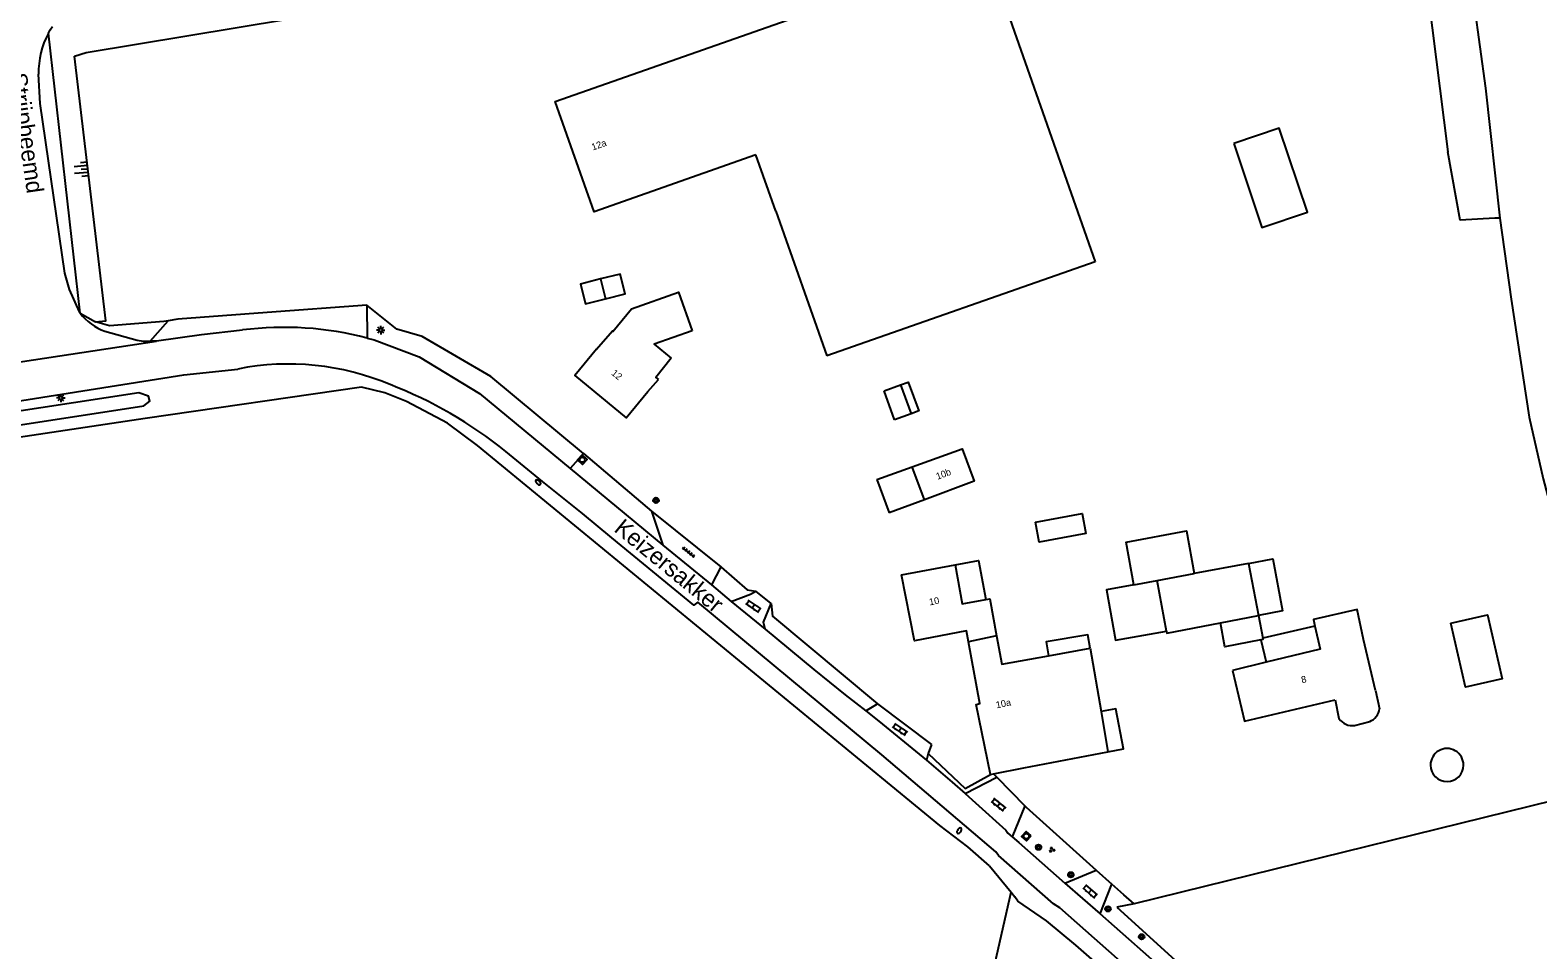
# Model space of a CAD drawing. Extents: x 124000 to 129000, y 395500 to 397503.
# Drawn here: x 126092.4 to 126314, y 397168.2 to 397303.4 of the extents above; entities that cross this region are included whole.
import ezdxf

# ---------------------------------------------------------------- set-up
doc = ezdxf.new("R2010")
doc.units = 0
for name, color, linetype in [('gg-afsc-draadraster', 7, 'Continuous'), ('gg-afsc-erfafscheiding', 7, 'Continuous'), ('gg-afsc-hekwerk', 7, 'Continuous'), ('gg-anno-huisnummerreeks BGT', 7, 'Continuous'), ('gg-anno-openbare ruimte label', 7, 'Continuous'), ('gg-bbg-bijgebouw', 7, 'Continuous'), ('gg-bbg-gedigitaliseerde bebouwing', 7, 'Continuous'), ('gg-bbg-gedigitaliseerde bijgebouw', 7, 'Continuous'), ('gg-bbg-hoofdgebouw', 7, 'Continuous'), ('gg-bbg-luifel en loopbrug', 7, 'Continuous'), ('gg-bbg-onder overbouw', 7, 'Continuous'), ('gg-bbg-pand overbouw', 7, 'Continuous'), ('gg-bbg-tussenscheiding', 7, 'Continuous'), ('gg-knt-BGT kruinlijn', 7, 'Continuous'), ('gg-knt-bovenkant onderkant talud', 7, 'Continuous'), ('gg-knt-bronhoudergrens', 7, 'Continuous'), ('gg-knt-verharding', 7, 'Continuous'), ('gg-knt-verharding nz', 7, 'Continuous'), ('gg-kntw-greppel-droge sloot', 7, 'Continuous'), ('gg-kwrk-keermuur', 7, 'Continuous'), ('gt-grn-weggrens', 7, 'Continuous'), ('gt-symb-boom', 7, 'Continuous'), ('gt-symb-brandkraan', 7, 'Continuous'), ('gt-symb-groenvak', 7, 'Continuous'), ('gt-symb-klinker verharding', 7, 'Continuous'), ('gt-symb-lichtmast', 7, 'Continuous'), ('gt-symb-rioolschacht', 7, 'Continuous'), ('gt-symb-talud symbool', 7, 'Continuous'), ('gt-symb-tegel verharding', 7, 'Continuous'), ('gx-grn-maaiveld', 7, 'Continuous')]:
    doc.layers.add(name, color=color, linetype=linetype)

# ---------------------------------------------------------------- blocks, each defined once
blk = doc.blocks.new('gt0-LMAST')
at = {"layer": 'gt-symb-lichtmast'}
for p, q in [((-0.18, 0.17), (-0.45, 0.44)), ((-0.01, 0.25), (-0.01, 0.62)), ((0.17, 0.17), (0.44, 0.44)), ((-0.26, 0), (-0.63, 0)), ((-0.18, -0.18), (-0.45, -0.45)), ((-0.01, -0.25), (-0.01, -0.63)), ((0.44, -0.45), (0.17, -0.18)), ((0.24, 0), (0.62, 0))]:
    blk.add_line(p, q, dxfattribs=at)
blk.add_circle((-0.01, 0), 0.25, dxfattribs=at)
blk = doc.blocks.new('gt0-TEG1')
at = {"layer": 'gt-symb-tegel verharding'}
for p, q in [((-1.12, 0), (1.13, 0)), ((-0.9, -0.25), (-0.9, 0.25)), ((-0.45, -0.25), (-0.45, 0.25)), ((0, -0.25), (0, 0.25)), ((0.45, -0.25), (0.45, 0.25)), ((0.9, -0.25), (0.9, 0.25))]:
    blk.add_line(p, q, dxfattribs=at)
blk = doc.blocks.new('gt0-BOOM')
at = {"layer": 'gt-symb-boom'}
for radius in [0.4, 0.2]:
    blk.add_circle((0, 0), radius, dxfattribs=at)
blk = doc.blocks.new('gt0-BR')
at = {"layer": 'gt-symb-brandkraan'}
for centre, radius, start, end in [((-0.24, 0), 0.206, 107.5669, 252.4331), ((0.6, -2.66), 3, 106.892, 107.5669), ((0, -0.69), 0.938, 73.108, 106.892), ((-0.6, -2.66), 3, 72.4331, 73.108), ((0.24, 0), 0.206, 287.567, 72.4331), ((0.6, 2.66), 3, 252.4331, 253.108), ((0, 0.69), 0.938, 253.108, 286.8921), ((-0.6, 2.66), 3, 286.8921, 287.567)]:
    blk.add_arc(centre, radius, start, end, dxfattribs=at)
blk = doc.blocks.new('gt0-RS')
at = {"layer": 'gt-symb-rioolschacht'}
blk.add_lwpolyline([(-0.5, -0.5), (0.5, -0.5), (0.5, 0.5), (-0.5, 0.5)], close=True, dxfattribs=at)
blk.add_circle((0, 0), 0.375, dxfattribs=at)
blk = doc.blocks.new('gt0-KL1')
at = {"layer": 'gt-symb-klinker verharding'}
for p, q in [((-1.15, 0.3), (1.15, 0.3)), ((-1, -0.3), (-1, 0.3)), ((-0.5, 0.3), (-0.5, 0.45)), ((0, -0.3), (0, 0.3)), ((0.5, 0.3), (0.5, 0.45)), ((1, -0.3), (1, 0.3)), ((-1.15, -0.3), (1.15, -0.3)), ((-0.5, -0.45), (-0.5, -0.3)), ((0.5, -0.45), (0.5, -0.3))]:
    blk.add_line(p, q, dxfattribs=at)
blk = doc.blocks.new('gt0-GRVAK')
at = {"layer": 'gt-symb-groenvak'}
for p, q in [((-0.11, 0.19), (-0.23, 0.24)), ((-0.18, 0.15), (0.09, 0.15)), ((-0.09, 0.21), (-0.16, 0.32)), ((-0.05, 0.21), (-0.05, 0.39)), ((0, 0.21), (0.06, 0.32)), ((0.01, 0.19), (0.13, 0.24)), ((0.26, -0.05), (0.2, 0.06)), ((0.3, -0.05), (0.3, 0.13)), ((0.35, -0.05), (0.41, 0.06)), ((-0.25, -0.23), (-0.36, -0.18)), ((-0.32, -0.26), (-0.05, -0.26)), ((-0.23, -0.21), (-0.29, -0.09)), ((-0.18, -0.2), (-0.18, -0.02)), ((-0.14, -0.21), (-0.07, -0.09)), ((-0.12, -0.23), (0, -0.18)), ((0.24, -0.07), (0.12, -0.02)), ((0.17, -0.11), (0.44, -0.11)), ((0.37, -0.07), (0.49, -0.02))]:
    blk.add_line(p, q, dxfattribs=at)
blk = doc.blocks.new('gt0-TALUD_1')
at = {"layer": 'gt-symb-talud symbool'}
for p, q in [((-1, -1), (-1, 0)), ((-0.5, -2), (-0.5, 0)), ((0, -1), (0, 0)), ((0.5, -2), (0.5, 0)), ((1, -1), (1, 0))]:
    blk.add_line(p, q, dxfattribs=at)

msp = doc.modelspace()

# ---------------------------------------------------------------- linework, layer by layer
at = {"layer": 'gg-afsc-draadraster'}
msp.add_lwpolyline([(126226.52, 397135.32), (126232.25, 397157.74), (126236.57, 397176.71)], dxfattribs=at)
at = {"layer": 'gg-afsc-erfafscheiding'}
for points in [[(126158.14, 397242.37), (126153.73, 397245.64), (126147.71, 397248.83), (126144.52, 397250.13), (126141.08, 397250.94), (126109.27, 397246.32), (126072.36, 397240.79), (125997.79, 397229.41), (125963.14, 397224.23), (125959.14, 397223.42)], [(126233.39, 397180.61), (126230.21, 397183.36), (126226.11, 397186.54), (126158.14, 397242.37)], [(126193.91, 397224.52), (126193.94, 397224.5), (126197.76, 397221.16), (126199.07, 397220.94)], [(126201.31, 397219.16), (126201.48, 397217.28), (126216.95, 397204.39)], [(126224.37, 397197.12), (126229.82, 397191.97), (126233.53, 397194.01)], [(126263.89, 397151.77), (126253.93, 397162.07), (126246.09, 397168.94), (126241.75, 397172.5), (126237.55, 397175.38), (126237.14, 397176.02)]]:
    msp.add_lwpolyline(points, dxfattribs=at)
at = {"layer": 'gg-afsc-hekwerk'}
for p, q in [((126141.86, 397262.97), (126127.21, 397261.91)), ((126141.86, 397262.97), (126127.21, 397261.91)), ((126233.97, 397194.1), (126234.45, 397193.62)), ((126233.97, 397194.1), (126234.45, 397193.62)), ((126234.45, 397193.62), (126238.61, 397189.42)), ((126234.45, 397193.62), (126238.61, 397189.42)), ((126238.61, 397189.42), (126238.8, 397189.23)), ((126238.61, 397189.42), (126238.8, 397189.23)), ((126233.39, 397180.61), (126236.57, 397176.71)), ((126249.08, 397179.97), (126251.39, 397177.91)), ((126249.08, 397179.97), (126251.39, 397177.91)), ((126236.57, 397176.71), (126237.14, 397176.02)), ((126253.14, 397176.35), (126251.39, 397177.91)), ((126253.14, 397176.35), (126251.39, 397177.91)), ((126254.64, 397175), (126253.14, 397176.35)), ((126254.64, 397175), (126253.14, 397176.35))]:
    msp.add_line(p, q, dxfattribs=at)
for points in [[(126173.72, 397241.21), (126160.1, 397252.51), (126150.02, 397258.38), (126146.27, 397259.46), (126141.86, 397262.97)], [(126173.72, 397241.21), (126160.1, 397252.51), (126150.02, 397258.38), (126146.27, 397259.46), (126141.86, 397262.97)], [(126112.68, 397260.68), (126112.05, 397260.57), (126104.05, 397259.94), (126102, 397260.54)], [(126112.68, 397260.68), (126112.05, 397260.57), (126104.05, 397259.94), (126102, 397260.54)], [(126127.21, 397261.91), (126114.08, 397260.95), (126112.68, 397260.68)], [(126127.21, 397261.91), (126114.08, 397260.95), (126112.68, 397260.68)], [(126238.8, 397189.23), (126239.27, 397188.75), (126249.08, 397179.97)], [(126238.8, 397189.23), (126239.27, 397188.75), (126249.08, 397179.97)]]:
    msp.add_lwpolyline(points, dxfattribs=at)
at = {"layer": 'gg-bbg-bijgebouw'}
for p, q in [((126271.49, 397225.04), (126263.5, 397223.55)), ((126267.33, 397216.32), (126272.93, 397217.39))]:
    msp.add_line(p, q, dxfattribs=at)
for points in [[(126254.63, 397221.89), (126250.58, 397221.13), (126251.92, 397213.76), (126259.39, 397215.1)], [(126259.39, 397215.1), (126259.44, 397214.8), (126267.33, 397216.32)]]:
    msp.add_lwpolyline(points, dxfattribs=at)
at = {"layer": 'gg-bbg-gedigitaliseerde bebouwing'}
for p, q in [((126220.47, 397223.36), (126228.34, 397224.84)), ((126242.08, 397211.46), (126248.18, 397212.57)), ((126248.18, 397212.57), (126249.79, 397203.26)), ((126290.12, 397206.37), (126290.74, 397203.65)), ((126249.79, 397203.26), (126250.81, 397197.35)), ((126284.21, 397204.98), (126284.76, 397202.23)), ((126287.06, 397201.21), (126289.29, 397201.8))]:
    msp.add_line(p, q, dxfattribs=at)
for points in [[(126228.34, 397224.84), (126229.39, 397219.08), (126232.86, 397219.71)], [(126232.86, 397219.71), (126233.45, 397219.82), (126234.44, 397214.39)], [(126234.44, 397214.39), (126235.2, 397210.21), (126242.08, 397211.46)]]:
    msp.add_lwpolyline(points, dxfattribs=at)
for centre, radius, start, end in [((126288.29, 397204.08), 2.49, 293.6854, 350.0439), ((126286.71, 397203.52), 2.33, 213.4183, 278.7814)]:
    msp.add_arc(centre, radius, start, end, dxfattribs=at)
at = {"layer": 'gg-bbg-gedigitaliseerde bijgebouw'}
for p, q in [((126176.2, 397266.84), (126176.94, 397263.93)), ((126217.89, 397250.38), (126220.33, 397251.27)), ((126219.43, 397246.15), (126217.89, 397250.38)), ((126220.33, 397251.27), (126221.87, 397247.04)), ((126221.87, 397247.04), (126219.43, 397246.15))]:
    msp.add_line(p, q, dxfattribs=at)
for points in [[(126176.94, 397263.93), (126179.84, 397264.67), (126179.11, 397267.57), (126176.2, 397266.84)], [(126240.14, 397231.09), (126247.02, 397232.38), (126247.57, 397229.43), (126240.69, 397228.15), (126240.14, 397231.09)], [(126254.63, 397221.89), (126253.46, 397228.16), (126262.33, 397229.82), (126263.5, 397223.55)], [(126271.49, 397225.04), (126275.03, 397225.71), (126276.46, 397218.05), (126272.93, 397217.39)], [(126301.22, 397216.27), (126306.59, 397217.49), (126308.73, 397208.07), (126303.36, 397206.84), (126301.22, 397216.27)]]:
    msp.add_lwpolyline(points, dxfattribs=at)
at = {"layer": 'gg-bbg-hoofdgebouw'}
for p, q in [((126201.97, 397276.79), (126199.06, 397285.08)), ((126201.97, 397276.79), (126209.47, 397255.53)), ((126248.92, 397269.36), (126209.47, 397255.53)), ((126183.18, 397250.3), (126184.75, 397252.07)), ((126290.12, 397206.37), (126288.35, 397213.87)), ((126274.06, 397210.51), (126269.12, 397209.31)), ((126238.43, 397195.01), (126250.81, 397197.35)), ((126233.53, 397194.01), (126233.97, 397194.1)), ((126233.97, 397194.1), (126238.43, 397195.01))]:
    msp.add_line(p, q, dxfattribs=at)
for points in [[(126199.06, 397285.08), (126175.29, 397276.71), (126169.53, 397292.94), (126232.87, 397315.18), (126248.92, 397269.36)], [(126180.76, 397262.47), (126187.7, 397264.91), (126189.7, 397259.21)], [(126175.64, 397256.51), (126177.96, 397259.21), (126178.04, 397259.13), (126180.76, 397262.47)], [(126189.7, 397259.21), (126184.09, 397257.24), (126186.61, 397255.19)], [(126175.64, 397256.51), (126172.46, 397252.66), (126180, 397246.44), (126183.18, 397250.3)], [(126186.61, 397255.19), (126184.36, 397252.38), (126184.75, 397252.07)], [(126222.02, 397239.22), (126229.36, 397241.86), (126231.12, 397237.1), (126223.82, 397234.38)], [(126230.3, 397213.5), (126230, 397215.12), (126222.35, 397213.65), (126220.47, 397223.36)], [(126288.35, 397213.87), (126287.42, 397218.24), (126281.01, 397216.77), (126281.24, 397215.79)], [(126281.24, 397215.79), (126282.01, 397212.43), (126274.06, 397210.51)], [(126233.53, 397194.01), (126231.43, 397204.31), (126231.95, 397204.43), (126230.3, 397213.5)], [(126269.12, 397209.31), (126270.88, 397201.83), (126284.21, 397204.98)]]:
    msp.add_lwpolyline(points, dxfattribs=at)
at = {"layer": 'gg-bbg-luifel en loopbrug'}
for p, q in [((126272.93, 397217.39), (126273.56, 397214.03)), ((126281.24, 397215.79), (126273.56, 397214.03)), ((126273.3, 397213.8), (126274.06, 397210.51))]:
    msp.add_line(p, q, dxfattribs=at)
for points in [[(126269.29, 397286.76), (126273.44, 397274.39), (126280.14, 397276.65), (126275.99, 397289.02), (126269.29, 397286.76)], [(126176.2, 397266.84), (126173.29, 397266.1), (126174.03, 397263.19), (126176.94, 397263.93)], [(126220.33, 397251.27), (126221.46, 397251.68), (126223, 397247.45), (126221.87, 397247.04)], [(126228.34, 397224.84), (126231.78, 397225.48), (126232.86, 397219.71)], [(126273.3, 397213.8), (126267.99, 397212.8), (126267.33, 397216.32)], [(126248.18, 397212.57), (126247.84, 397214.54), (126241.73, 397213.49), (126242.08, 397211.46)], [(126273.56, 397214.03), (126273.59, 397213.85), (126273.3, 397213.8)], [(126250.81, 397197.35), (126253.07, 397197.77), (126251.95, 397203.67), (126249.79, 397203.26)]]:
    msp.add_lwpolyline(points, dxfattribs=at)
for start, end in [(359.9882, 180.0118), (180.0118, 359.9882)]:
    msp.add_arc((126300.65, 397195.4), 2.43, start, end, dxfattribs=at)
at = {"layer": 'gg-bbg-onder overbouw'}
msp.add_line((126223.82, 397234.38), (126222.02, 397239.22), dxfattribs=at)
at = {"layer": 'gg-bbg-pand overbouw'}
for p, q in [((126216.83, 397237.35), (126222.02, 397239.22)), ((126216.83, 397237.35), (126218.64, 397232.46)), ((126223.82, 397234.38), (126218.64, 397232.46))]:
    msp.add_line(p, q, dxfattribs=at)
at = {"layer": 'gg-bbg-tussenscheiding'}
for p, q in [((126271.49, 397225.04), (126272.93, 397217.39)), ((126258.06, 397222.53), (126263.5, 397223.55)), ((126254.63, 397221.89), (126258.06, 397222.53)), ((126259.39, 397215.1), (126258.06, 397222.53)), ((126234.44, 397214.39), (126230.3, 397213.5))]:
    msp.add_line(p, q, dxfattribs=at)
at = {"layer": 'gg-knt-BGT kruinlijn'}
msp.add_lwpolyline([(126308.42, 397275.79), (126307.67, 397275.79), (126302.56, 397275.47), (126300.77, 397285.52)], dxfattribs=at)
at = {"layer": 'gg-knt-bovenkant onderkant talud'}
for q in [(126095.06, 397302.97), (126102, 397260.54)]:
    msp.add_line((126099.74, 397261.82), q, dxfattribs=at)
msp.add_lwpolyline([(126293.79, 397395.2), (126298.38, 397354.34), (126303.79, 397313.16), (126306.32, 397294.88), (126308.42, 397275.79)], dxfattribs=at)
at = {"layer": 'gg-knt-bronhoudergrens'}
msp.add_line((126254.64, 397175), (126252.1, 397174.52), dxfattribs=at)
msp.add_lwpolyline([(126252.1, 397174.52), (126303.2, 397128.09), (126353.01, 397081.26), (126413.83, 397022.02), (126414.81, 397024.58)], dxfattribs=at)
at = {"layer": 'gg-knt-verharding'}
for p, q in [((126093.87, 397292.63), (126093.61, 397296.95)), ((126097.45, 397267.69), (126093.87, 397292.63)), ((126110.03, 397257.68), (126112.68, 397260.68)), ((126110.94, 397257.7), (126110.03, 397257.68)), ((126173.72, 397241.21), (126183.71, 397232.73)), ((126171.73, 397238.97), (126185.38, 397227.7)), ((126183.71, 397232.73), (126193.91, 397224.52)), ((126183.71, 397232.73), (126185.38, 397227.7)), ((126185.38, 397227.7), (126192.54, 397221.88)), ((126193.91, 397224.52), (126192.54, 397221.88)), ((126192.54, 397221.88), (126195.44, 397219.43)), ((126195.44, 397219.43), (126198.28, 397220.5)), ((126198.28, 397220.5), (126199.07, 397220.94)), ((126195.44, 397219.43), (126200.44, 397215.36)), ((126200.15, 397216.42), (126201.31, 397219.16)), ((126200.44, 397215.36), (126200.15, 397216.42)), ((126215.22, 397203.36), (126216.95, 397204.39)), ((126224.86, 397198.43), (126224.37, 397197.12)), ((126224.37, 397197.12), (126224.11, 397196.12)), ((126229.82, 397191.2), (126234.45, 397193.62)), ((126238.61, 397189.42), (126236.75, 397184.85)), ((126244.47, 397178.04), (126249.08, 397179.97)), ((126244.47, 397178.04), (126249.68, 397173.52)), ((126249.68, 397173.52), (126251.39, 397177.91))]:
    msp.add_line(p, q, dxfattribs=at)
for points in [[(126095.06, 397302.97), (126095.34, 397303.46), (126095.64, 397303.94)], [(126099.74, 397261.82), (126099.61, 397262), (126098.15, 397265.27), (126097.45, 397267.69)], [(126103.35, 397259.19), (126108.1, 397257.83), (126109.06, 397257.72), (126110.03, 397257.68)], [(126123.6, 397259.34), (126117.58, 397258.62), (126110.94, 397257.7)], [(126141.92, 397258.16), (126142.94, 397257.9), (126149.55, 397255.4), (126158.41, 397249.99), (126171.73, 397238.97)], [(125958.2, 397228.34), (125962.28, 397229.22), (125992.91, 397234), (126026.9, 397239.18), (126058.86, 397244.07), (126087.1, 397248.36), (126114.98, 397252.77), (126122.9, 397253.6)], [(126217.59, 397196.91), (126190.53, 397219.34), (126189.93, 397218.9), (126177.9, 397228.81), (126173.58, 397232.38), (126167.7, 397237.09), (126162.31, 397241.5)], [(126200.44, 397215.36), (126207.55, 397209.45), (126212.2, 397205.7), (126215.22, 397203.36)], [(126215.22, 397203.36), (126217.15, 397201.86), (126224.11, 397196.12)], [(126266.34, 397154.53), (126254.78, 397164.69), (126243.73, 397174.44), (126242.8, 397175.02), (126234.71, 397182.1), (126234.31, 397182.63), (126217.59, 397196.91)], [(126224.11, 397196.12), (126227.89, 397192.88), (126229.82, 397191.2)], [(126229.82, 397191.2), (126231.35, 397189.87), (126235.8, 397185.84), (126236.11, 397185.4), (126236.75, 397184.85)], [(126236.75, 397184.85), (126237.69, 397184.04), (126244.47, 397178.04)], [(126412.65, 397020.19), (126402.84, 397029.7), (126384.03, 397047.69), (126340.43, 397089.56), (126316.44, 397112.57), (126296.69, 397131.4), (126283.17, 397143.79), (126268.6, 397156.78), (126249.68, 397173.52)]]:
    msp.add_lwpolyline(points, dxfattribs=at)
for centre, radius, start, end in [((126101.53, 397300.33), 15.33, 108.6415, 192.8607), ((126105.74, 397297.21), 12.13, 151.6659, 181.2355), ((126105.88, 397266.45), 7.7, 217.0392, 250.8005), ((126129.68, 397211.31), 48.42, 75.3633, 97.224), ((126130.36, 397216.07), 38.27, 67.0601, 101.2429), ((126122.5, 397192.07), 63.47, 51.1553, 68.9665)]:
    msp.add_arc(centre, radius, start, end, dxfattribs=at)
at = {"layer": 'gg-knt-verharding nz'}
for p, q in [((126141.86, 397262.97), (126141.92, 397258.16)), ((126173.72, 397241.21), (126171.73, 397238.97))]:
    msp.add_line(p, q, dxfattribs=at)
at = {"layer": 'gg-kntw-greppel-droge sloot'}
msp.add_lwpolyline([(125999.23, 397233.43), (125961.51, 397227.67), (125960.4, 397226.55), (125960.47, 397225.84), (125961.71, 397225.35), (125998.72, 397231.25), (126037.73, 397237.22), (126109.09, 397248.21), (126109.99, 397248.9), (126109.75, 397249.61), (126108.36, 397250.1), (126074.06, 397244.88), (126037.6, 397239.47), (125999.23, 397233.43)], dxfattribs=at)
at = {"layer": 'gg-kwrk-keermuur'}
msp.add_line((126290.12, 397370.3), (126300.77, 397285.52), dxfattribs=at)
for points in [[(126098.9, 397299.59), (126100.61, 397300.11), (126181.7, 397313.59), (126232.6, 397330.93), (126226.47, 397382.19)], [(126102, 397260.54), (126103.49, 397260.69), (126098.9, 397299.59)]]:
    msp.add_lwpolyline(points, dxfattribs=at)
at = {"layer": 'gt-grn-weggrens'}
for p, q in [((126081.9, 397253.31), (126110.94, 397257.7)), ((126201.31, 397219.16), (126199.07, 397220.94)), ((126216.95, 397204.39), (126224.86, 397198.43))]:
    msp.add_line(p, q, dxfattribs=at)
at = {"layer": 'gx-grn-maaiveld'}
msp.add_lwpolyline([(126308.42, 397275.79), (126310.09, 397263.89), (126312.7, 397246.54), (126314.76, 397237.48), (126326.66, 397192.75), (126254.64, 397175)], dxfattribs=at)

# ---------------------------------------------------------------- block references
at = {"layer": 'gt-symb-boom'}
for p in [(126184.37, 397234.3), (126240.61, 397183.33), (126245.35, 397179.27), (126250.82, 397174.26), (126255.76, 397170.17)]:
    msp.add_blockref('gt0-BOOM', p, dxfattribs=at)
at = {"layer": 'gt-symb-brandkraan'}
for p, rotation in [((126167.05, 397236.94), -44.4065191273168), ((126228.94, 397185.76), 52.74434866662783)]:
    msp.add_blockref('gt0-BR', p, dxfattribs=dict(at, rotation=rotation))
at = {"layer": 'gt-symb-groenvak'}
msp.add_blockref('gt0-GRVAK', (126242.55, 397182.97), dxfattribs=at)
at = {"layer": 'gt-symb-klinker verharding'}
for p, rotation in [((126198.67, 397218.74), -34.246011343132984), ((126220.22, 397200.63), -34.246011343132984), ((126234.71, 397189.56), -38.82982490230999), ((126248.17, 397176.84), -40.98653320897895)]:
    msp.add_blockref('gt0-KL1', p, dxfattribs=dict(at, rotation=rotation))
at = {"layer": 'gt-symb-lichtmast'}
for p in [(126143.91, 397259.33), (126096.88, 397249.36)]:
    msp.add_blockref('gt0-LMAST', p, dxfattribs=at)
at = {"layer": 'gt-symb-rioolschacht'}
for p, rotation in [((126173.54, 397240.28), -132.89389072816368), ((126238.81, 397184.95), 138.7709507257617)]:
    msp.add_blockref('gt0-RS', p, dxfattribs=dict(at, rotation=rotation))
at = {"layer": 'gt-symb-talud symbool', "xscale": 1.0002399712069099, "yscale": 1.00023997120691, "rotation": -84.72259391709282}
msp.add_blockref('gt0-TALUD_1', (126100.86, 397283.05), dxfattribs=at)
at = {"layer": 'gt-symb-tegel verharding', "rotation": 141.0450397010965}
msp.add_blockref('gt0-TEG1', (126189.17, 397226.68), dxfattribs=at)

# ---------------------------------------------------------------- texts
at = {"layer": 'gg-anno-huisnummerreeks BGT'}
for s, rotation, p in [('12a', 19.6, (126175.1, 397285.71)), ('12', 320.5, (126177.73, 397252.85)), ('10b', 20.4, (126225.75, 397237.32)), ('10', 11, (126224.62, 397218.86)), ('8', 13.3, (126279.34, 397207.42)), ('10a', 11.5, (126234.44, 397203.73))]:
    msp.add_text(s, height=1, rotation=rotation, dxfattribs=at).set_placement(p)
at = {"layer": 'gg-anno-openbare ruimte label'}
for s, rotation, p in [('Strijpbeemd', 278.2, (126089.37, 397296.95)), ('Keizersakker', 320.7, (126178.05, 397229.85))]:
    msp.add_text(s, height=2.5, rotation=rotation, dxfattribs=at).set_placement(p)

doc.saveas('drawing.dxf')
